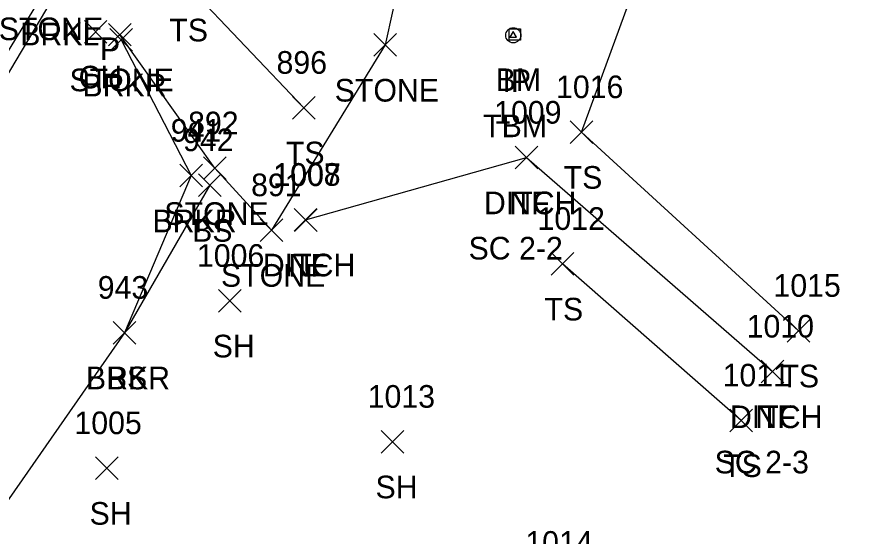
# Model space of a CAD drawing. Extents: x 1528286 to 1556263, y 492387 to 508952.
# Drawn here: x 1528636.2 to 1528710.1, y 492686.8 to 492732.7 of the extents above; entities that cross this region are included whole.
import ezdxf

# ---------------------------------------------------------------- set-up
doc = ezdxf.new("R2010")
doc.units = 0
for name, color, linetype in [('C_A', 7, 'Continuous'), ('CPBM', 7, 'Continuous'), ('D_A', 7, 'Continuous'), ('D_I', 7, 'Continuous'), ('D_TIC', 7, 'Continuous'), ('DD', 7, 'Continuous'), ('L_A', 7, 'Continuous'), ('L_C', 7, 'Continuous'), ('L_I', 7, 'Continuous'), ('L_TIC', 7, 'Continuous'), ('LASF', 7, 'Continuous'), ('LAWE', 7, 'Continuous'), ('LELB', 7, 'Continuous'), ('M_A', 7, 'Continuous'), ('M_C', 7, 'Continuous'), ('MPIR', 7, 'Continuous')]:
    doc.layers.add(name, color=color, linetype=linetype)

msp = doc.modelspace()

# ---------------------------------------------------------------- linework, layer by layer
at = {"layer": 'CPBM'}
for p, q in [((1528679.712, 492730.608), (1528679.712, 492731.608)), ((1528679.712, 492731.608), (1528680.712, 492731.608)), ((1528679.712, 492730.608), (1528679.712, 492731.608)), ((1528679.712, 492731.608), (1528680.712, 492731.608)), ((1528680.712, 492731.608), (1528680.712, 492730.608)), ((1528680.712, 492731.608), (1528680.712, 492730.608)), ((1528680.712, 492730.608), (1528679.712, 492730.608)), ((1528680.712, 492730.608), (1528679.712, 492730.608)), ((1528680.215, 492731.109), (1528680.215, 492731.109)), ((1528680.215, 492731.109), (1528680.215, 492731.109)), ((1528680.215, 492731.109), (1528680.215, 492731.109)), ((1528680.215, 492731.109), (1528680.215, 492731.109))]:
    msp.add_line(p, q, dxfattribs=at)
at = {"layer": 'D_TIC'}
for points in [[(1528680.248, 492719.236), (1528682.248, 492721.236)], [(1528682.248, 492719.236), (1528680.248, 492721.236)], [(1528680.248, 492719.236), (1528682.248, 492721.236)], [(1528682.248, 492719.236), (1528680.248, 492721.236)], [(1528660.725, 492713.748), (1528662.725, 492715.748)], [(1528662.725, 492713.748), (1528660.725, 492715.748)], [(1528660.725, 492713.748), (1528662.725, 492715.748)], [(1528662.725, 492713.748), (1528660.725, 492715.748)], [(1528701.981, 492700.344), (1528703.981, 492702.344)], [(1528703.981, 492700.344), (1528701.981, 492702.344)], [(1528701.981, 492700.344), (1528703.981, 492702.344)], [(1528703.981, 492700.344), (1528701.981, 492702.344)]]:
    msp.add_lwpolyline(points, dxfattribs=at)
at = {"layer": 'DD'}
msp.add_lwpolyline([(1528661.725, 492714.748), (1528681.248, 492720.236), (1528702.981, 492701.344)], dxfattribs=at)
msp.add_lwpolyline([(1528661.725, 492714.748), (1528681.248, 492720.236), (1528702.981, 492701.344)], dxfattribs=at)
at = {"layer": 'L_TIC'}
for points in [[(1528642.198, 492730.345), (1528644.198, 492732.345)], [(1528644.198, 492730.345), (1528642.198, 492732.345)], [(1528642.198, 492730.345), (1528644.198, 492732.345)], [(1528644.198, 492730.345), (1528642.198, 492732.345)], [(1528644.341, 492730.093), (1528646.341, 492732.093)], [(1528646.341, 492730.093), (1528644.341, 492732.093)], [(1528644.341, 492730.093), (1528646.341, 492732.093)], [(1528646.341, 492730.093), (1528644.341, 492732.093)], [(1528644.438, 492729.638), (1528646.438, 492731.638)], [(1528646.438, 492729.638), (1528644.438, 492731.638)], [(1528644.438, 492729.638), (1528646.438, 492731.638)], [(1528646.438, 492729.638), (1528644.438, 492731.638)], [(1528667.765, 492729.184), (1528669.765, 492731.184)], [(1528669.765, 492729.184), (1528667.765, 492731.184)], [(1528667.765, 492729.184), (1528669.765, 492731.184)], [(1528669.765, 492729.184), (1528667.765, 492731.184)], [(1528660.587, 492723.641), (1528662.587, 492725.641)], [(1528662.587, 492723.641), (1528660.587, 492725.641)], [(1528660.587, 492723.641), (1528662.587, 492725.641)], [(1528662.587, 492723.641), (1528660.587, 492725.641)], [(1528685.116, 492721.486), (1528687.116, 492723.486)], [(1528687.116, 492721.486), (1528685.116, 492723.486)], [(1528685.116, 492721.486), (1528687.116, 492723.486)], [(1528687.116, 492721.486), (1528685.116, 492723.486)], [(1528680.248, 492719.236), (1528682.248, 492721.236)], [(1528682.248, 492719.236), (1528680.248, 492721.236)], [(1528680.248, 492719.236), (1528682.248, 492721.236)], [(1528682.248, 492719.236), (1528680.248, 492721.236)], [(1528652.721, 492718.292), (1528654.721, 492720.292)], [(1528654.721, 492718.292), (1528652.721, 492720.292)], [(1528652.721, 492718.292), (1528654.721, 492720.292)], [(1528654.721, 492718.292), (1528652.721, 492720.292)], [(1528650.622, 492717.642), (1528652.622, 492719.642)], [(1528652.622, 492717.642), (1528650.622, 492719.642)], [(1528650.622, 492717.642), (1528652.622, 492719.642)], [(1528652.622, 492717.642), (1528650.622, 492719.642)], [(1528652.271, 492716.805), (1528654.271, 492718.805)], [(1528654.271, 492716.805), (1528652.271, 492718.805)], [(1528652.271, 492716.805), (1528654.271, 492718.805)], [(1528654.271, 492716.805), (1528652.271, 492718.805)], [(1528660.754, 492713.723), (1528662.754, 492715.723)], [(1528662.754, 492713.723), (1528660.754, 492715.723)], [(1528660.754, 492713.723), (1528662.754, 492715.723)], [(1528662.754, 492713.723), (1528660.754, 492715.723)], [(1528657.721, 492712.827), (1528659.721, 492714.827)], [(1528659.721, 492712.827), (1528657.721, 492714.827)], [(1528657.721, 492712.827), (1528659.721, 492714.827)], [(1528659.721, 492712.827), (1528657.721, 492714.827)], [(1528683.423, 492709.851), (1528685.423, 492711.851)], [(1528685.423, 492709.851), (1528683.423, 492711.851)], [(1528683.423, 492709.851), (1528685.423, 492711.851)], [(1528685.423, 492709.851), (1528683.423, 492711.851)], [(1528654.045, 492706.589), (1528656.045, 492708.589)], [(1528656.045, 492706.589), (1528654.045, 492708.589)], [(1528654.045, 492706.589), (1528656.045, 492708.589)], [(1528656.045, 492706.589), (1528654.045, 492708.589)], [(1528644.743, 492703.772), (1528646.743, 492705.772)], [(1528646.743, 492703.772), (1528644.743, 492705.772)], [(1528644.743, 492703.772), (1528646.743, 492705.772)], [(1528646.743, 492703.772), (1528644.743, 492705.772)], [(1528644.743, 492703.772), (1528646.743, 492705.772)], [(1528646.743, 492703.772), (1528644.743, 492705.772)], [(1528644.743, 492703.772), (1528646.743, 492705.772)], [(1528646.743, 492703.772), (1528644.743, 492705.772)], [(1528704.259, 492703.943), (1528706.259, 492705.943)], [(1528706.259, 492703.943), (1528704.259, 492705.943)], [(1528704.259, 492703.943), (1528706.259, 492705.943)], [(1528706.259, 492703.943), (1528704.259, 492705.943)], [(1528701.981, 492700.344), (1528703.981, 492702.344)], [(1528703.981, 492700.344), (1528701.981, 492702.344)], [(1528701.981, 492700.344), (1528703.981, 492702.344)], [(1528703.981, 492700.344), (1528701.981, 492702.344)], [(1528699.204, 492696.025), (1528701.204, 492698.025)], [(1528701.204, 492696.025), (1528699.204, 492698.025)], [(1528699.204, 492696.025), (1528701.204, 492698.025)], [(1528701.204, 492696.025), (1528699.204, 492698.025)], [(1528668.424, 492694.145), (1528670.424, 492696.145)], [(1528670.424, 492694.145), (1528668.424, 492696.145)], [(1528668.424, 492694.145), (1528670.424, 492696.145)], [(1528670.424, 492694.145), (1528668.424, 492696.145)], [(1528643.171, 492691.811), (1528645.171, 492693.811)], [(1528645.171, 492691.811), (1528643.171, 492693.811)], [(1528643.171, 492691.811), (1528645.171, 492693.811)], [(1528645.171, 492691.811), (1528643.171, 492693.811)]]:
    msp.add_lwpolyline(points, dxfattribs=at)
at = {"layer": 'LASF'}
msp.add_lwpolyline([(1528639.098, 492735.608), (1528627.241, 492716.245), (1528613.209, 492719.227), (1528607.642, 492721.098), (1528613.116, 492733.507), (1528630.781, 492745.216), (1528656.998, 492750.434), (1528671.474, 492742.478), (1528668.765, 492730.184), (1528658.721, 492713.827), (1528653.721, 492719.292), (1528645.341, 492731.093)], dxfattribs=at)
msp.add_lwpolyline([(1528639.098, 492735.608), (1528627.241, 492716.245), (1528613.209, 492719.227), (1528607.642, 492721.098), (1528613.116, 492733.507), (1528630.781, 492745.216), (1528656.998, 492750.434), (1528671.474, 492742.478), (1528668.765, 492730.184), (1528658.721, 492713.827), (1528653.721, 492719.292), (1528645.341, 492731.093)], dxfattribs=at)
at = {"layer": 'LAWE'}
for points in [[(1528639.893, 492735.148), (1528628.638, 492716.197), (1528619.322, 492697.772), (1528600.014, 492685.78), (1528586.494, 492675.208), (1528555.765, 492651.711), (1528552.059, 492644.142), (1528537.626, 492632.534), (1528523.345, 492621.851), (1528510.87, 492609.533), (1528497.291, 492599.489), (1528482.777, 492583.151), (1528460.774, 492562.048), (1528436.992, 492551.704), (1528418.951, 492545.204), (1528399.482, 492529.93), (1528387.952, 492519.312), (1528358.196, 492480.955)], [(1528639.893, 492735.148), (1528628.638, 492716.197), (1528619.322, 492697.772), (1528600.014, 492685.78), (1528586.494, 492675.208), (1528555.765, 492651.711), (1528552.059, 492644.142), (1528537.626, 492632.534), (1528523.345, 492621.851), (1528510.87, 492609.533), (1528497.291, 492599.489), (1528482.777, 492583.151), (1528460.774, 492562.048), (1528436.992, 492551.704), (1528418.951, 492545.204), (1528399.482, 492529.93), (1528387.952, 492519.312), (1528358.196, 492480.955)], [(1528645.438, 492730.638), (1528651.622, 492718.642), (1528645.743, 492704.772), (1528631.806, 492684.8), (1528615.475, 492671.091), (1528597.131, 492648.324), (1528570.323, 492633.929), (1528549.926, 492614.136), (1528527.115, 492580.823), (1528486.911, 492550.694), (1528466.236, 492548.442), (1528453.392, 492536.119), (1528428.919, 492520.065), (1528405.493, 492507.44), (1528391.912, 492487.091), (1528384.545, 492464.65)], [(1528645.438, 492730.638), (1528651.622, 492718.642), (1528645.743, 492704.772), (1528631.806, 492684.8), (1528615.475, 492671.091), (1528597.131, 492648.324), (1528570.323, 492633.929), (1528549.926, 492614.136), (1528527.115, 492580.823), (1528486.911, 492550.694), (1528466.236, 492548.442), (1528453.392, 492536.119), (1528428.919, 492520.065), (1528405.493, 492507.44), (1528391.912, 492487.091), (1528384.545, 492464.65)]]:
    msp.add_lwpolyline(points, dxfattribs=at)
at = {"layer": 'LELB'}
for points in [[(1528705.259, 492704.943), (1528686.116, 492722.486), (1528693.638, 492743.104), (1528696.254, 492760.067), (1528714.163, 492764.9), (1528717.514, 492785.825)], [(1528705.259, 492704.943), (1528686.116, 492722.486), (1528693.638, 492743.104), (1528696.254, 492760.067), (1528714.163, 492764.9), (1528717.514, 492785.825)], [(1528661.587, 492724.641), (1528651.291, 492735.499), (1528637.79, 492741.092), (1528626.005, 492739.602), (1528615.037, 492725.446), (1528613.03, 492719.826)], [(1528661.587, 492724.641), (1528651.291, 492735.499), (1528637.79, 492741.092), (1528626.005, 492739.602), (1528615.037, 492725.446), (1528613.03, 492719.826)], [(1528653.271, 492717.805), (1528645.743, 492704.772), (1528631.806, 492684.8), (1528615.475, 492671.091), (1528597.131, 492648.324), (1528570.323, 492633.929), (1528549.926, 492614.136), (1528527.115, 492580.823), (1528486.911, 492550.694), (1528472.867, 492532.388)], [(1528653.271, 492717.805), (1528645.743, 492704.772), (1528631.806, 492684.8), (1528615.475, 492671.091), (1528597.131, 492648.324), (1528570.323, 492633.929), (1528549.926, 492614.136), (1528527.115, 492580.823), (1528486.911, 492550.694), (1528472.867, 492532.388)], [(1528700.204, 492697.025), (1528684.423, 492710.851)], [(1528700.204, 492697.025), (1528684.423, 492710.851)]]:
    msp.add_lwpolyline(points, dxfattribs=at)
at = {"layer": 'MPIR'}
msp.add_lwpolyline([(1528680.078, 492731.371), (1528679.789, 492730.871), (1528680.366, 492730.871)], close=True, dxfattribs=at)
msp.add_lwpolyline([(1528680.078, 492731.371), (1528679.789, 492730.871), (1528680.366, 492730.871)], close=True, dxfattribs=at)
msp.add_circle((1528680.078, 492731.038), 0.667, dxfattribs=at)
msp.add_circle((1528680.078, 492731.038), 0.667, dxfattribs=at)

# ---------------------------------------------------------------- texts
at = {"layer": 'C_A'}
msp.add_text('BM', height=2, dxfattribs=at).set_placement((1528678.53, 492726.109))
msp.add_text('BM', height=2, dxfattribs=at).set_placement((1528678.53, 492726.109))
at = {"layer": 'D_A'}
for s, p in [('P', (1528643.576, 492728.843)), ('P', (1528643.576, 492728.843)), ('DITCH', (1528677.484, 492715.236)), ('DITCH', (1528677.484, 492715.236)), ('DITCH', (1528657.961, 492709.748)), ('DITCH', (1528657.961, 492709.748)), ('DITCH', (1528699.218, 492696.344)), ('DITCH', (1528699.218, 492696.344))]:
    msp.add_text(s, height=2, dxfattribs=at).set_placement(p)
at = {"layer": 'D_I'}
for s, p in [('1009', (1528678.39, 492723.236)), ('1009', (1528678.39, 492723.236)), ('1008', (1528658.874, 492717.748)), ('1008', (1528658.874, 492717.748)), ('1010', (1528700.69, 492704.344)), ('1010', (1528700.69, 492704.344))]:
    msp.add_text(s, height=2, dxfattribs=at).set_placement(p)
at = {"layer": 'L_A'}
for s, p in [('STONE', (1528634.641, 492730.608)), ('STONE', (1528634.641, 492730.608)), ('BRKL', (1528636.539, 492730.148)), ('BRKL', (1528636.539, 492730.148)), ('TS', (1528649.701, 492730.499)), ('TS', (1528649.701, 492730.499)), ('CH', (1528641.686, 492726.345)), ('CH', (1528641.686, 492726.345)), ('STONE', (1528640.885, 492726.093)), ('STONE', (1528640.885, 492726.093)), ('BRKR', (1528642.028, 492725.638)), ('BRKR', (1528642.028, 492725.638)), ('STONE', (1528664.308, 492725.184)), ('STONE', (1528664.308, 492725.184)), ('TS', (1528659.997, 492719.641)), ('TS', (1528659.997, 492719.641)), ('TS', (1528684.525, 492717.486)), ('TS', (1528684.525, 492717.486)), ('NF', (1528679.729, 492715.236)), ('NF', (1528679.729, 492715.236)), ('BRKR', (1528648.213, 492713.642)), ('BRKR', (1528648.213, 492713.642)), ('STONE', (1528649.264, 492714.292)), ('STONE', (1528649.264, 492714.292)), ('BS', (1528651.712, 492712.805)), ('BS', (1528651.712, 492712.805)), ('NF', (1528660.235, 492709.723)), ('NF', (1528660.235, 492709.723)), ('STONE', (1528654.264, 492708.827)), ('STONE', (1528654.264, 492708.827)), ('TS', (1528682.833, 492705.851)), ('TS', (1528682.833, 492705.851)), ('SH', (1528653.534, 492702.589)), ('SH', (1528653.534, 492702.589)), ('BRKR', (1528642.334, 492699.772)), ('BRKR', (1528642.334, 492699.772)), ('BS', (1528644.184, 492699.772)), ('BS', (1528644.184, 492699.772)), ('TS', (1528703.669, 492699.943)), ('TS', (1528703.669, 492699.943)), ('NF', (1528701.462, 492696.344)), ('NF', (1528701.462, 492696.344)), ('TS', (1528698.614, 492692.025)), ('TS', (1528698.614, 492692.025)), ('SH', (1528667.913, 492690.145)), ('SH', (1528667.913, 492690.145)), ('SH', (1528642.66, 492687.811)), ('SH', (1528642.66, 492687.811))]:
    msp.add_text(s, height=2, dxfattribs=at).set_placement(p)
at = {"layer": 'L_C'}
for s, p in [('SC 2-2', (1528676.13, 492711.236)), ('SC 2-2', (1528676.13, 492711.236)), ('SC 2-3', (1528697.863, 492692.344)), ('SC 2-3', (1528697.863, 492692.344))]:
    msp.add_text(s, height=2, dxfattribs=at).set_placement(p)
at = {"layer": 'L_I'}
for s, p in [('896', (1528659.17, 492727.641)), ('896', (1528659.17, 492727.641)), ('1016', (1528683.856, 492725.486)), ('1016', (1528683.856, 492725.486)), ('1009', (1528678.39, 492723.236)), ('1009', (1528678.39, 492723.236)), ('892', (1528651.359, 492722.292)), ('892', (1528651.359, 492722.292)), ('941', (1528649.827, 492721.642)), ('941', (1528649.827, 492721.642)), ('942', (1528650.909, 492720.805)), ('942', (1528650.909, 492720.805)), ('1007', (1528658.904, 492717.723)), ('1007', (1528658.904, 492717.723)), ('891', (1528656.926, 492716.827)), ('891', (1528656.926, 492716.827)), ('1012', (1528682.218, 492713.851)), ('1012', (1528682.218, 492713.851)), ('1006', (1528652.14, 492710.589)), ('1006', (1528652.14, 492710.589)), ('943', (1528643.381, 492707.772)), ('943', (1528643.381, 492707.772)), ('943', (1528643.381, 492707.772)), ('943', (1528643.381, 492707.772)), ('1015', (1528703.055, 492707.943)), ('1015', (1528703.055, 492707.943)), ('1010', (1528700.69, 492704.344)), ('1010', (1528700.69, 492704.344)), ('1011', (1528698.567, 492700.025)), ('1011', (1528698.567, 492700.025)), ('1013', (1528667.22, 492698.145)), ('1013', (1528667.22, 492698.145)), ('1005', (1528641.321, 492695.811)), ('1005', (1528641.321, 492695.811)), ('1014', (1528681.142, 492685.247)), ('1014', (1528681.142, 492685.247))]:
    msp.add_text(s, height=2, dxfattribs=at).set_placement(p)
at = {"layer": 'M_A'}
msp.add_text('IP', height=2, dxfattribs=at).set_placement((1528679.125, 492726.038))
msp.add_text('IP', height=2, dxfattribs=at).set_placement((1528679.125, 492726.038))
at = {"layer": 'M_C'}
msp.add_text('TBM', height=2, dxfattribs=at).set_placement((1528677.416, 492722.038))
msp.add_text('TBM', height=2, dxfattribs=at).set_placement((1528677.416, 492722.038))

doc.saveas('drawing.dxf')
